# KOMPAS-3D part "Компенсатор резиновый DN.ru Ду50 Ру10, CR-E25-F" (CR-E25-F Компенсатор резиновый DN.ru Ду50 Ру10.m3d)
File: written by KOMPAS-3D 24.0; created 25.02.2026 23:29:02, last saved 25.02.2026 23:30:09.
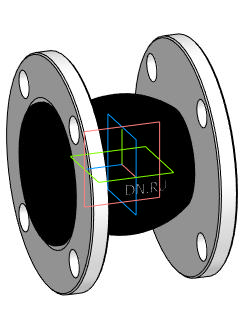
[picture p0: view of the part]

Document properties: Автор: DN.RU; Полное имя файла: D:\PROJECT CAD\DN.RU\...178(4)(ACTUALE). CR-E25-F Компенсатор резиновый DN.ru Ру10-16\DN50_PN10\CR-E25-F Компенсатор резиновый DN.ru Ду50 Ру10.m3d

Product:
- Body: Твердое тело2  | qty 1
    Масса: 4.895928
- Part/product: Компенсатор резиновый DN.ru Ду50 Ру10  | designation CR-E25-F
    Масса: 4.62
    Раздел спецификации: Прочие изделия
    Комментарий: D140-02162
    Примечание: D140-02162
    additional columns: Типовые

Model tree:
1. Твердое тело2  (labels: Твердое тело2)

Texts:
  CR-E25-F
